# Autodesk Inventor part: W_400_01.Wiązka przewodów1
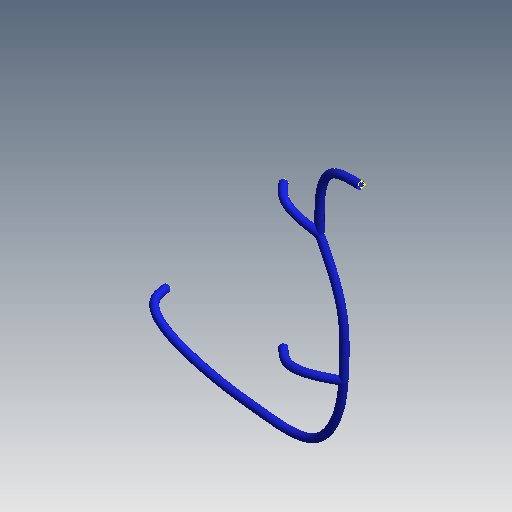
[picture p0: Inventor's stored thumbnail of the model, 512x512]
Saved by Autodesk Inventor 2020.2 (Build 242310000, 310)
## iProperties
Manager: www.cadconsulting.pl
Company: Fabian Stasiak CAD Consulting
Created: 2014-10
Part Number: W_400_01.Wiązka przewodów1
Material: Ogólne
Document SubType Name: Modelowanie
Designer: F.Stasiak
Appearance: Ogólne
Catalog Web Link: www.expertbooks.pl
GlobalPropertyList: <PropertyList/>
Key:2|1|1|0|4|0|0|0|4|0|0|0|Level:2: <CableProperty entityType="Connector" version="1.0"><ID editable="" value=""/><UserDefined/><Name editable="True" value=""/><Refdes editable="True" value="LISTW
Author: F.Stasiak
Subject: Zbiór ćwiczeń. Autodesk Inventor 2020. Kurs Professional
## Parameters: d4 = 0, d5 = 0, d6 = 0, d7 = 0, d8 = 0, d9 = 0, d10 = 0, d11 = 0, d12 = 0, d13 = 0
